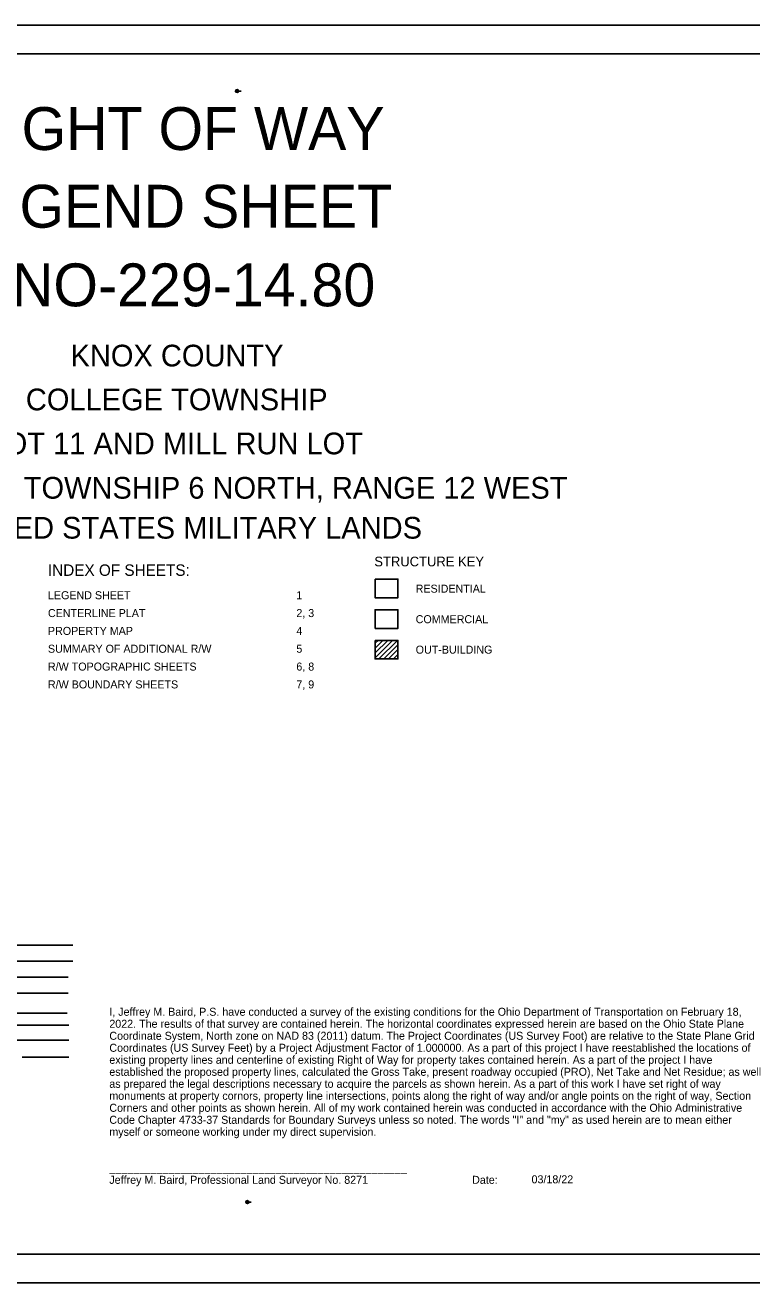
# Model space of a CAD drawing. Extents: x 0 to 104, y 0 to 37.
# Drawn here: x 13.29 to 26.01, y 0 to 22 of the extents above; entities that cross this region are included whole.
import ezdxf

# ---------------------------------------------------------------- set-up
doc = ezdxf.new("R2010")
doc.units = 0
for name, color, linetype in [('SC_Scratch3', 7, 'Continuous'), ('SH_Border', 7, 'Continuous'), ('SH_Cut_Line', 7, 'Continuous'), ('SH_Data', 7, 'Continuous'), ('SH_Masking', 7, 'Continuous'), ('SH_Named_Boundary', 7, 'Continuous')]:
    doc.layers.add(name, color=color, linetype=linetype)

# ---------------------------------------------------------------- blocks, each defined once
blk = doc.blocks.new('STRUC_KEY')
at = {"layer": 'SH_Data'}
for p, q in [((-1.005, -1.38), (-1.003, -1.379)), ((-1.005, -1.43), (-0.953, -1.379)), ((-1.005, -1.515), (-0.868, -1.379)), ((-1.005, -1.6), (-0.784, -1.379)), ((-1.005, -1.685), (-0.699, -1.379)), ((-0.94, -1.705), (-0.614, -1.379)), ((-0.855, -1.705), (-0.607, -1.457)), ((-1.005, -1.7), (-1, -1.705)), ((-0.771, -1.705), (-0.607, -1.542)), ((-0.686, -1.705), (-0.607, -1.626))]:
    blk.add_line(p, q, dxfattribs=at)
for points in [[(-1.005, -0.308), (-0.607, -0.308), (-0.607, -0.634), (-1.005, -0.634)], [(-1.005, -1.379), (-0.607, -1.379), (-0.607, -1.705), (-1.005, -1.705)]]:
    blk.add_lwpolyline(points, close=True, dxfattribs=at)
at = {"layer": 'SH_Masking'}
blk.add_lwpolyline([(-1.005, -1.17), (-0.607, -1.17), (-0.607, -0.844), (-1.005, -0.844)], close=True, dxfattribs=at)
at = {"layer": 'SH_Data'}
for s, height, p in [('STRUCTURE KEY', 0.17, (-1.02, -0.085)), ('RESIDENTIAL', 0.14, (-0.296, -0.545)), ('COMMERCIAL', 0.14, (-0.296, -1.079)), ('OUT-BUILDING', 0.14, (-0.296, -1.612))]:
    blk.add_text(s, height=height, dxfattribs=at).set_placement(p)

msp = doc.modelspace()

# ---------------------------------------------------------------- linework, layer by layer
at = {"layer": 'SC_Scratch3'}
msp.add_lwpolyline([(0, 0), (34, 0), (34, 22), (0, 22)], close=True, dxfattribs=at)
at = {"layer": 'SH_Border'}
for p, q in [((16.974, 20.848), (17.026, 20.848)), ((17, 20.848), (17.072, 20.848)), ((17.155, 1.413), (17.207, 1.413)), ((17.181, 1.413), (17.247, 1.413))]:
    msp.add_line(p, q, dxfattribs=at)
for centre in [(17, 20.848), (17.181, 1.413)]:
    msp.add_circle(centre, 0.026, dxfattribs=at)
at = {"layer": 'SH_Data'}
for p, q in [((10.645, 5.908), (14.129, 5.908)), ((10.645, 5.628), (14.129, 5.628)), ((10.145, 5.348), (14.045, 5.348)), ((10.145, 5.068), (14.045, 5.068)), ((9.677, 4.718), (14.027, 4.718)), ((12.275, 4.508), (14.057, 4.508)), ((12.275, 4.244), (14.057, 4.244)), ((13.241, 3.948), (14.057, 3.948))]:
    msp.add_line(p, q, dxfattribs=at)
at = {"layer": 'SH_Named_Boundary'}
msp.add_lwpolyline([(1.5, 21.5), (33.5, 21.5), (33.5, 0.5), (1.5, 0.5)], close=True, dxfattribs=at)

# ---------------------------------------------------------------- block references
at = {"layer": 'SH_Data'}
msp.add_blockref('STRUC_KEY', (20.422, 12.618), dxfattribs=at)

# ---------------------------------------------------------------- texts
at = {"layer": 'SH_Border'}
for s, p in [('1', (16.999, 20.854)), ('R/W Legend Sheet', (17.033, 20.854)), ('CUSTOM 1:2640', (17.033, 20.838)), ('3', (17.18, 1.419)), ('Drawing', (17.214, 1.419)), ('CUSTOM 1.12:1', (17.214, 1.403))]:
    msp.add_text(s, height=0.00328, dxfattribs=at).set_placement(p)
at = {"layer": 'SH_Cut_Line'}
for s, height, p in [('RIGHT OF WAY', 0.75, (12.227, 19.816)), ('LEGEND SHEET', 0.75, (11.968, 18.457)), ('KNO-229-14.80', 0.75, (12.394, 17.082)), ('      KNOX COUNTY      ', 0.38, (13.24, 16.03)), ('COLLEGE TOWNSHIP', 0.38, (13.305, 15.262)), ('LOT 11 AND MILL RUN LOT ', 0.38, (12.653, 14.493)), ('INDEX OF SHEETS:', 0.2, (13.692, 12.367)), ('LEGEND SHEET                       ', 0.14, (13.692, 11.958)), ('1     ', 0.14, (18.038, 11.958)), ('CENTERLINE PLAT                    ', 0.14, (13.692, 11.646)), ('2, 3', 0.14, (18.038, 11.646)), ('PROPERTY MAP                       ', 0.14, (13.692, 11.334)), ('4', 0.14, (18.038, 11.334)), ('SUMMARY OF ADDITIONAL R/W          ', 0.14, (13.692, 11.022)), ('5', 0.14, (18.038, 11.022)), ('R/W TOPOGRAPHIC SHEETS             ', 0.14, (13.692, 10.71)), ('6, 8', 0.14, (18.038, 10.71)), ('R/W BOUNDARY SHEETS                ', 0.14, (13.692, 10.398)), ('7, 9', 0.14, (18.038, 10.398))]:
    msp.add_text(s, height=height, dxfattribs=at).set_placement(p)
at = {"layer": 'SH_Data'}
for s, height, p in [('QUARTER 1, TOWNSHIP 6 NORTH, RANGE 12 WEST', 0.38, (10.078, 13.717)), ('UNITED STATES MILITARY LANDS', 0.38, (11.907, 13.018)), ('I, Jeffrey M. Baird, P.S. have conducted a survey of the existing conditions for the Ohio Department of Transportation on February 18, ', 0.14, (14.766, 4.672)), ('2022. The results of that survey are contained herein. The horizontal coordinates expressed herein are based on the Ohio State Plane ', 0.14, (14.766, 4.462)), ('Coordinate System, North zone on NAD 83 (2011) datum. The Project Coordinates (US Survey Foot) are relative to the State Plane Grid ', 0.14, (14.766, 4.252)), ('Coordinates (US Survey Feet) by a Project Adjustment Factor of 1.000000. As a part of this project I have reestablished the locations of ', 0.14, (14.766, 4.042)), ('existing property lines and centerline of existing Right of Way for property takes contained herein. As a part of the project I have ', 0.14, (14.766, 3.832)), ('established the proposed property lines, calculated the Gross Take, present roadway occupied (PRO), Net Take and Net Residue; as well ', 0.14, (14.766, 3.622)), ('as prepared the legal descriptions necessary to acquire the parcels as shown herein. As a part of this work I have set right of way ', 0.14, (14.766, 3.412)), ('monuments at property cornors, property line intersections, points along the right of way and/or angle points on the right of way, Section ', 0.14, (14.766, 3.202)), ('Corners and other points as shown herein. All of my work contained herein was conducted in accordance with the Ohio Administrative ', 0.14, (14.766, 2.992)), ('Code Chapter 4733-37 Standards for Boundary Surveys unless so noted. The words "I" and "my" as used herein are to mean either ', 0.14, (14.766, 2.782)), ('myself or someone working under my direct supervision.', 0.14, (14.766, 2.572)), ('__________________________________________________', 0.14, (14.766, 1.942)), ('Jeffrey M. Baird, Professional Land Surveyor No. 8271                                   Date:                  ', 0.14, (14.766, 1.732)), ('03/18/22', 0.14, (22.153, 1.741))]:
    msp.add_text(s, height=height, dxfattribs=at).set_placement(p)

doc.saveas('drawing.dxf')
